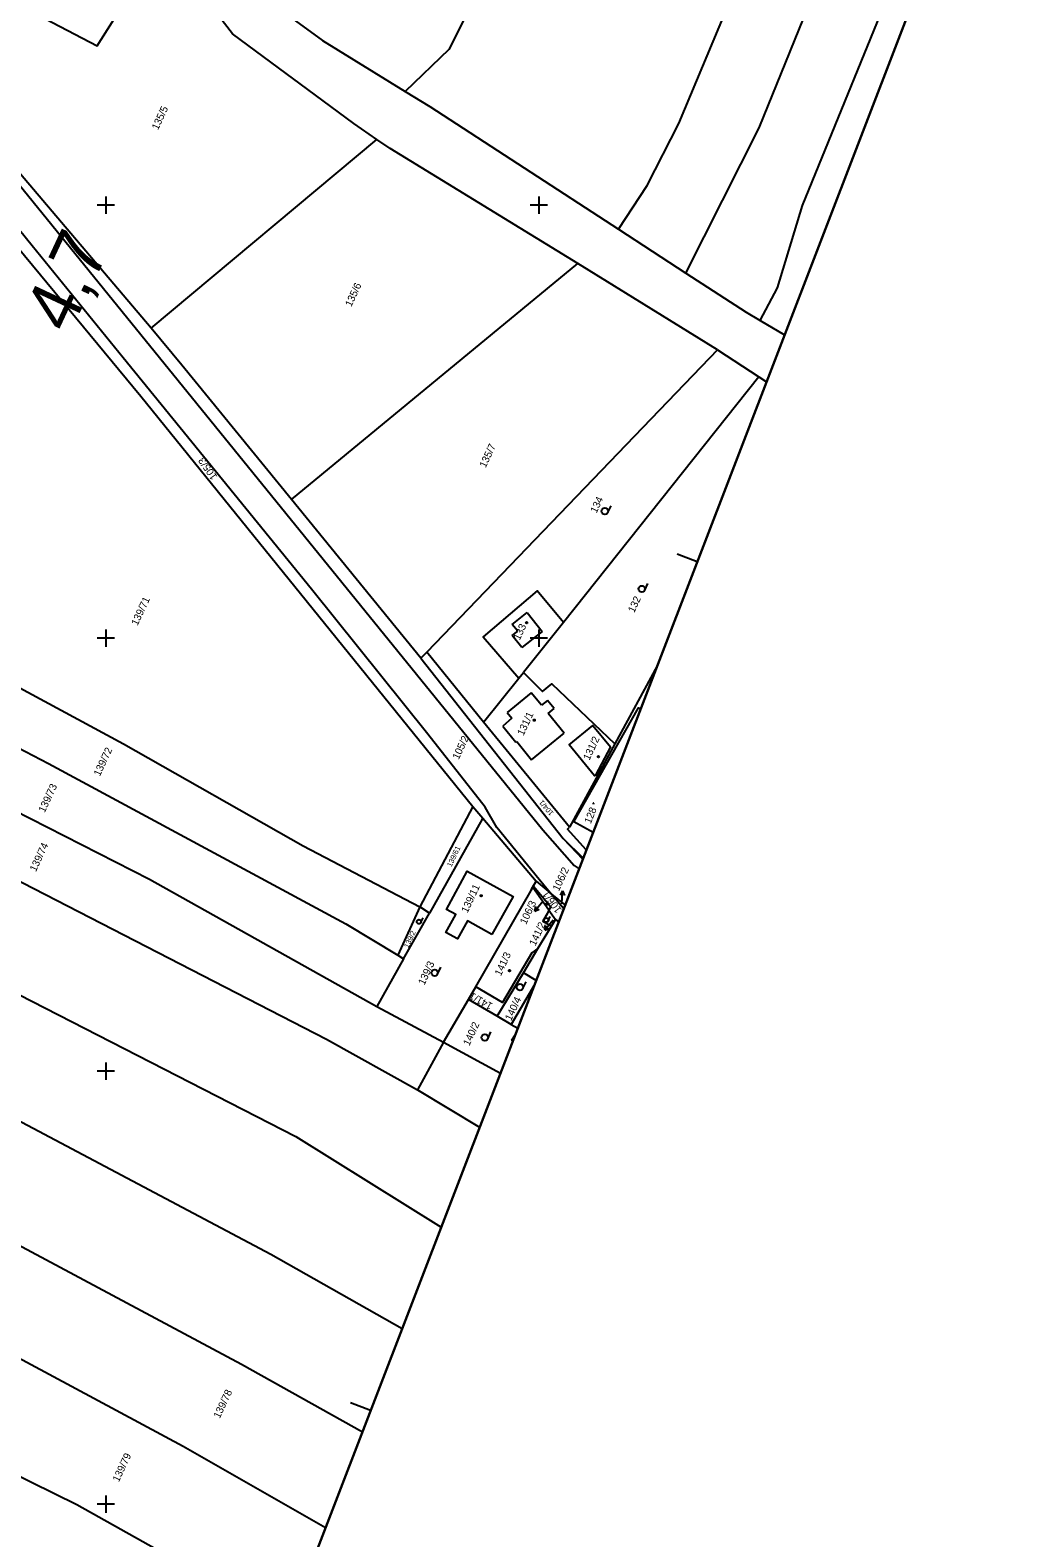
# Model space of a CAD drawing. Extents: x -755344 to -754412, y -1162670 to -1161477.
# Drawn here: x -754717.5 to -754488, y -1162307.8 to -1161959.6 of the extents above; entities that cross this region are included whole.
import ezdxf

# ---------------------------------------------------------------- set-up
doc = ezdxf.new("R2010")
doc.units = 0
for name, color, linetype in [('Formát', 7, 'Continuous'), ('Staniceni a namezniky', 7, 'Continuous'), ('Síť', 7, 'Continuous'), ('Vrstva 55', 7, 'Continuous'), ('Vrstva 56', 7, 'Continuous'), ('Vrstva 57', 7, 'Continuous'), ('Vrstva 58', 7, 'Continuous'), ('Vrstva 59', 7, 'Continuous')]:
    doc.layers.add(name, color=color, linetype=linetype)

msp = doc.modelspace()

# ---------------------------------------------------------------- linework, layer by layer
at = {"layer": 'Formát'}
for p, q in [((-754563.43, -1162082.36), (-754568.1, -1162080.56)), ((-754638.86, -1162278.35), (-754643.53, -1162276.55))]:
    msp.add_line(p, q, dxfattribs=at)
msp.add_lwpolyline([(-754488.01, -1161886.37), (-754789.71, -1162670.32), (-755344.08, -1162456.97), (-755042.37, -1161673.02)], close=True, dxfattribs=at)
for points in [[(-755344.08, -1162456.97), (-754789.71, -1162670.32), (-754488.01, -1161886.37), (-755042.37, -1161673.02)], [(-755344.08, -1162456.97), (-754789.71, -1162670.32), (-754488.01, -1161886.37), (-755042.37, -1161673.02)], [(-754789.71, -1162670.32), (-754488.01, -1161886.37), (-755042.37, -1161673.02), (-755344.08, -1162456.97)]]:
    msp.add_lwpolyline(points, dxfattribs=at)
at = {"layer": 'Síť'}
for points in [[(-754698, -1162000), (-754700, -1162000), (-754702, -1162000)], [(-754700, -1161998), (-754700, -1162000), (-754700, -1162002)], [(-754598, -1162000), (-754600, -1162000), (-754602, -1162000)], [(-754600, -1161998), (-754600, -1162000), (-754600, -1162002)], [(-754700, -1162098), (-754700, -1162100), (-754700, -1162102)], [(-754600, -1162098), (-754600, -1162100), (-754600, -1162102)], [(-754698, -1162100), (-754700, -1162100), (-754702, -1162100)], [(-754598, -1162100), (-754600, -1162100), (-754602, -1162100)], [(-754700, -1162198), (-754700, -1162200), (-754700, -1162202)], [(-754698, -1162200), (-754700, -1162200), (-754702, -1162200)], [(-754698, -1162300), (-754700, -1162300), (-754702, -1162300)], [(-754700, -1162298), (-754700, -1162300), (-754700, -1162302)]]:
    msp.add_lwpolyline(points, dxfattribs=at)
at = {"layer": 'Vrstva 55'}
for p, q in [((-754649.99, -1161962), (-754630.9, -1161973.72)), ((-754649.99, -1161962), (-754630.9, -1161973.72)), ((-754689.56, -1162028.42), (-754731.42, -1161979.09)), ((-754689.56, -1162028.42), (-754637.39, -1161984.8)), ((-754581.59, -1162005.57), (-754566.03, -1162015.68)), ((-754581.59, -1162005.57), (-754566.03, -1162015.68)), ((-754657.11, -1162067.99), (-754590.97, -1162013.45)), ((-754558.74, -1162033.37), (-754590.97, -1162013.45)), ((-754682.41, -1162036.96), (-754689.56, -1162028.42)), ((-754558.74, -1162033.37), (-754625.87, -1162103.25)), ((-754558.74, -1162033.37), (-754549.21, -1162039.61)), ((-754657.11, -1162067.99), (-754682.41, -1162036.96)), ((-754549.21, -1162039.61), (-754594.32, -1162096.35)), ((-754549.21, -1162039.61), (-754547.43, -1162040.77)), ((-754627.26, -1162104.59), (-754657.11, -1162067.99)), ((-754594.32, -1162096.35), (-754603.58, -1162107.92)), ((-754625.87, -1162103.25), (-754627.26, -1162104.59)), ((-754627.26, -1162104.59), (-754594.4, -1162146.25)), ((-754612.76, -1162119.38), (-754625.87, -1162103.25)), ((-754604.64, -1162109.25), (-754603.58, -1162107.92)), ((-754572.68, -1162106.38), (-754582.49, -1162124.43)), ((-754612.76, -1162119.38), (-754604.64, -1162109.25)), ((-754592.91, -1162143.6), (-754612.76, -1162119.38)), ((-754582.49, -1162124.43), (-754592.91, -1162143.6)), ((-754615.21, -1162138.87), (-754627.49, -1162162.07)), ((-754615.21, -1162138.87), (-754612.93, -1162141.56)), ((-754612.93, -1162141.56), (-754600.62, -1162156.1)), ((-754600.62, -1162156.1), (-754601.47, -1162157.47)), ((-754600.62, -1162156.1), (-754597.36, -1162158.77)), ((-754601.47, -1162157.47), (-754601.38, -1162157.59)), ((-754597.66, -1162162.82), (-754601.38, -1162157.59)), ((-754627.49, -1162162.07), (-754632.53, -1162173.22)), ((-754631.23, -1162174.04), (-754625.29, -1162163.5)), ((-754625.29, -1162163.5), (-754627.49, -1162162.07)), ((-754597.66, -1162162.82), (-754596.14, -1162164.94)), ((-754600.21, -1162171.69), (-754597.06, -1162166.46)), ((-754597.06, -1162166.46), (-754596.14, -1162164.94)), ((-754631.23, -1162174.04), (-754637.42, -1162185.04)), ((-754632.53, -1162173.22), (-754631.23, -1162174.04)), ((-754603.57, -1162177.26), (-754600.21, -1162171.69)), ((-754609.61, -1162187.26), (-754603.57, -1162177.26)), ((-754600.64, -1162179.04), (-754603.57, -1162177.26)), ((-754616.28, -1162183.45), (-754614.58, -1162180.53)), ((-754600.96, -1162179.88), (-754606.37, -1162189.2)), ((-754637.42, -1162185.04), (-754622, -1162193.28)), ((-754622, -1162193.28), (-754616.28, -1162183.45)), ((-754609.61, -1162187.26), (-754616.28, -1162183.45)), ((-754606.37, -1162189.2), (-754609.61, -1162187.26)), ((-754606.37, -1162189.2), (-754604.89, -1162190.08)), ((-754622, -1162193.28), (-754608.89, -1162200.48)), ((-754628.02, -1162204.3), (-754613.67, -1162212.89))]:
    msp.add_line(p, q, dxfattribs=at)
for points in [[(-754573.32, -1161853.54), (-754575.25, -1161857.88), (-754609.39, -1161941.34), (-754620.82, -1161964.09), (-754630.9, -1161973.72)], [(-754581.59, -1162005.57), (-754574.99, -1161995.43), (-754567.68, -1161981.15), (-754555.59, -1161952.23), (-754538.63, -1161903.69), (-754525.17, -1161872.07)], [(-754566.03, -1162015.68), (-754549.09, -1161982.12), (-754515.32, -1161898.89), (-754506.22, -1161879.36)], [(-754548.91, -1162026.6), (-754544.92, -1162019.1), (-754539.09, -1162000.11), (-754515.76, -1161942.9), (-754491.63, -1161884.98)], [(-754717.5, -1161955.11), (-754702.03, -1161963.19), (-754686.04, -1161937.95)], [(-754637.39, -1161984.8), (-754642.71, -1161981.11), (-754670.75, -1161960.4), (-754682.08, -1161945.77), (-754686.04, -1161937.95)], [(-754669.27, -1161943.74), (-754668.12, -1161945.6), (-754662.1, -1161953.11), (-754649.99, -1161962)], [(-754669.27, -1161943.74), (-754668.12, -1161945.6), (-754662.1, -1161953.11), (-754649.99, -1161962)], [(-754630.9, -1161973.72), (-754625.17, -1161977.24), (-754581.59, -1162005.57)], [(-754630.9, -1161973.72), (-754625.17, -1161977.24), (-754581.59, -1162005.57)], [(-754597.36, -1162158.77), (-754599.91, -1162155.71), (-754609.7, -1162143.74), (-754612.4, -1162138.98), (-754625.61, -1162122.15), (-754652.5, -1162088.7), (-754680.12, -1162054.72), (-754695.96, -1162035.25), (-754716.99, -1162009.36), (-754740.8, -1161980.09), (-754741.4, -1161980.31), (-754743.83, -1161981.19)], [(-754742.02, -1161983.57), (-754691.91, -1162044.14), (-754615.21, -1162138.87)], [(-754590.97, -1162013.45), (-754634.36, -1161986.91), (-754637.39, -1161984.8)], [(-754566.03, -1162015.68), (-754552.14, -1162024.71), (-754548.91, -1162026.6)], [(-754566.03, -1162015.68), (-754552.14, -1162024.71), (-754548.91, -1162026.6)], [(-754548.91, -1162026.6), (-754543.25, -1162029.91)], [(-754548.91, -1162026.6), (-754543.25, -1162029.91)], [(-754785.12, -1162078.33), (-754739.17, -1162101.03), (-754695.9, -1162124.41), (-754654.4, -1162147.91), (-754627.49, -1162162.07)], [(-754789.45, -1162089.23), (-754713.23, -1162128.96), (-754644.57, -1162165.98), (-754632.53, -1162173.22)], [(-754594.32, -1162096.35), (-754600.38, -1162089.08), (-754612.9, -1162099.72), (-754604.64, -1162109.25)], [(-754794.8, -1162102.72), (-754733.16, -1162133.64), (-754689.89, -1162155.62), (-754637.42, -1162185.04)], [(-754603.58, -1162107.92), (-754599.13, -1162112.3), (-754596.97, -1162110.52), (-754582.49, -1162124.43)], [(-754799.86, -1162115.47), (-754745.23, -1162143.07), (-754649.07, -1162192.57), (-754628.02, -1162204.3)], [(-754587.49, -1162144.88), (-754591.9, -1162142.38), (-754577.01, -1162116.08), (-754576.52, -1162116.37)], [(-754583.48, -1162125.12), (-754586.89, -1162131.6), (-754587.13, -1162131.76), (-754593.02, -1162124.61), (-754587.57, -1162120.16), (-754583.48, -1162125.12)], [(-754808.43, -1162137.05), (-754656.15, -1162215.06), (-754622.57, -1162236.02)], [(-754612.93, -1162141.56), (-754613.06, -1162141.78), (-754625.29, -1162163.5)], [(-754594.4, -1162146.25), (-754589.78, -1162150.81)], [(-754594.4, -1162146.25), (-754589.87, -1162151.05)], [(-754589.04, -1162148.89), (-754593.36, -1162144.13), (-754592.91, -1162143.6)], [(-754610.85, -1162168.44), (-754616.5, -1162165.29), (-754618.79, -1162169.4), (-754621.47, -1162167.95), (-754619.16, -1162163.81), (-754621.3, -1162162.63), (-754616.57, -1162153.8), (-754605.95, -1162159.62), (-754610.85, -1162168.44)], [(-754601.38, -1162157.59), (-754601.21, -1162157.29), (-754597.24, -1162162.07), (-754597.66, -1162162.82)], [(-754614.58, -1162180.53), (-754601.76, -1162158.25), (-754601.47, -1162157.47)], [(-754593.93, -1162161.59), (-754597.36, -1162158.77)], [(-754594.27, -1162162.48), (-754597.36, -1162158.77)], [(-754817.91, -1162160.94), (-754773.06, -1162183.36), (-754661.89, -1162242.23), (-754631.58, -1162259.43)], [(-754597.66, -1162162.82), (-754598.11, -1162163.63), (-754599.08, -1162165.36), (-754597.06, -1162166.46)], [(-754596.14, -1162164.94), (-754595.44, -1162165.51)], [(-754600.21, -1162171.69), (-754601.66, -1162172.69), (-754608.41, -1162184.14), (-754614.58, -1162180.53)], [(-754827.93, -1162185.11), (-754743.71, -1162227.55), (-754668.64, -1162267.68), (-754640.75, -1162283.26)], [(-754606, -1162192.95), (-754606.25, -1162192.8), (-754605.43, -1162191.48)], [(-754837.67, -1162208.02), (-754737.97, -1162256.6), (-754682.13, -1162286.58), (-754649.24, -1162305.33)], [(-754657.78, -1162327.52), (-754706.68, -1162300.09), (-754748.68, -1162279.47), (-754846.58, -1162228.99)]]:
    msp.add_lwpolyline(points, dxfattribs=at)
at = {"layer": 'Vrstva 56'}
for p, q in [((-754721.12, -1161993.95), (-754599.09, -1162144.22)), ((-754606.16, -1162096.83), (-754602.72, -1162094.03)), ((-754602.72, -1162094.03), (-754599.22, -1162098.47)), ((-754604.83, -1162098.34), (-754606.16, -1162096.83)), ((-754606.14, -1162099.38), (-754604.83, -1162098.34)), ((-754603.92, -1162102.18), (-754606.14, -1162099.38)), ((-754599.22, -1162098.47), (-754603.92, -1162102.18)), ((-754601.76, -1162112.63), (-754607.35, -1162117.18)), ((-754599.41, -1162115.5), (-754601.76, -1162112.63)), ((-754598, -1162114.35), (-754599.41, -1162115.5)), ((-754596.48, -1162116.22), (-754598, -1162114.35)), ((-754606.27, -1162118.5), (-754608.35, -1162120.28)), ((-754607.35, -1162117.18), (-754606.27, -1162118.5)), ((-754597.89, -1162117.37), (-754596.48, -1162116.22)), ((-754594.15, -1162121.96), (-754597.89, -1162117.37)), ((-754608.35, -1162120.28), (-754605.29, -1162124.02)), ((-754601.67, -1162128.07), (-754594.15, -1162121.96)), ((-754605.29, -1162124.02), (-754605.12, -1162123.88)), ((-754605.12, -1162123.88), (-754601.67, -1162128.07)), ((-754599.09, -1162144.22), (-754591.81, -1162152.45)), ((-754591.81, -1162152.45), (-754590.72, -1162153.25)), ((-754601.76, -1162158.25), (-754601.38, -1162157.59)), ((-754622, -1162193.28), (-754628.02, -1162204.3))]:
    msp.add_line(p, q, dxfattribs=at)
at = {"layer": 'Vrstva 57'}
for p, q in [((-754599.03, -1162160.7), (-754600.96, -1162163)), ((-754594.54, -1162158.36), (-754595.1, -1162159.33)), ((-754594.73, -1162161.36), (-754594.54, -1162158.36)), ((-754594.54, -1162158.36), (-754594.1, -1162159.4)), ((-754600.96, -1162163), (-754600.7, -1162161.91)), ((-754600.96, -1162163), (-754599.93, -1162162.55)), ((-754596.67, -1162165.12), (-754598.6, -1162167.42)), ((-754598.6, -1162167.42), (-754598.34, -1162166.33)), ((-754598.6, -1162167.42), (-754597.57, -1162166.98))]:
    msp.add_line(p, q, dxfattribs=at)
at = {"layer": 'Vrstva 58'}
for p, q in [((-754584.07, -1162070.98), (-754583.33, -1162069.4)), ((-754575.56, -1162088.94), (-754574.82, -1162087.36)), ((-754597.86, -1162165.33), (-754597.36, -1162164.26)), ((-754627.23, -1162165.68), (-754626.73, -1162164.61)), ((-754623.38, -1162177.57), (-754622.64, -1162175.99)), ((-754603.69, -1162180.91), (-754602.95, -1162179.33)), ((-754611.81, -1162192.5), (-754611.07, -1162190.92))]:
    msp.add_line(p, q, dxfattribs=at)
for centre, radius in [((-754584.75, -1162070.67), 0.75), ((-754576.24, -1162088.63), 0.75), ((-754627.69, -1162165.46), 0.502), ((-754598.31, -1162165.11), 0.502), ((-754624.06, -1162177.26), 0.75), ((-754604.37, -1162180.6), 0.75), ((-754612.49, -1162192.19), 0.75)]:
    msp.add_circle(centre, radius, dxfattribs=at)
at = {"layer": 'Vrstva 59'}
msp.add_line((-754587.42, -1162138.34), (-754587.31, -1162138.05), dxfattribs=at)
for centre in [(-754602.8, -1162096.4), (-754601.07, -1162118.92), (-754586.24, -1162127.34), (-754613.32, -1162159.48), (-754598.24, -1162161.47), (-754606.78, -1162176.76)]:
    msp.add_circle(centre, 0.175, dxfattribs=at)
msp.add_arc((-754587.29, -1162138.23), 0.175, 99.0834, 218.8179, dxfattribs=at)

# ---------------------------------------------------------------- texts
at = {"layer": 'Staniceni a namezniky'}
msp.add_text('4,7', height=12, rotation=64.9752, dxfattribs=at).set_placement((-754708.38, -1162029.97))
at = {"layer": 'Vrstva 57'}
for s, height, rotation, p in [('135/5', 1.7, 65, (-754687.95, -1161982.76)), ('135/6', 1.7, 65, (-754643.31, -1162023.59)), ('135/7', 1.7, 65, (-754612.29, -1162060.77)), ('105/3', 1.7, 124.8536, (-754674.15, -1162062.7)), ('134', 1.7, 65, (-754586.69, -1162071.25)), ('139/71', 1.7, 65, (-754692.69, -1162097.23)), ('132', 1.7, 65, (-754577.98, -1162094.24)), ('133', 1.7, 65, (-754604.44, -1162100.6)), ('131/1', 1.7, 65, (-754603.57, -1162122.65)), ('105/2', 1.7, 65, (-754618.52, -1162128.16)), ('139/72', 1.7, 65, (-754701.38, -1162132.01)), ('131/2', 1.7, 65, (-754588.33, -1162128.33)), ('139/73', 1.7, 65, (-754714.12, -1162140.41)), ('104/1', 1.2, 130.6051, (-754596.49, -1162140.36)), ('128', 1.7, 67.8956, (-754588.03, -1162142.98)), ('139/74', 1.7, 65, (-754716.15, -1162154.04)), ('139/61', 1.2, 65, (-754620.2, -1162152.93)), ('106/2', 1.7, 65, (-754595.39, -1162158.54)), ('139/11', 1.7, 65, (-754616.49, -1162163.59)), ('106/3', 1.7, 65, (-754602.95, -1162166.24)), ('106/1', 1.7, 125.9798, (-754594.63, -1162162.72)), ('139/2', 1.2, 65, (-754630.15, -1162171.65)), ('141/2', 1.7, 65, (-754600.81, -1162171.2)), ('139/3', 1.7, 65, (-754626.44, -1162180.24)), ('141/3', 1.7, 65, (-754608.78, -1162178.13)), ('141/1', 1.7, 150.6824, (-754610.51, -1162184.45)), ('140/4', 1.7, 65, (-754606.4, -1162188.48)), ('140/2', 1.7, 65, (-754616.07, -1162194.27)), ('139/78', 1.7, 65, (-754673.7, -1162280.3)), ('139/79', 1.7, 65, (-754697.01, -1162294.98))]:
    msp.add_text(s, height=height, rotation=rotation, dxfattribs=at).set_placement(p)

doc.saveas('drawing.dxf')
